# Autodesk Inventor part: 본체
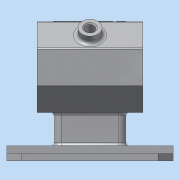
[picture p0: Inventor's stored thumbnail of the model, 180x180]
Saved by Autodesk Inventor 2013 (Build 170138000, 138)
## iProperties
Created: 2018-06
Part Number: 본체
Material: 알루미늄 6061
Document SubType Name: Modeling
Designer: Administrator
Density: 2.71 g/cm^3
Mass: 554.043 g
Surface Area: 601.935 cm^2
Volume: 204.444 cm^3
Author: Administrator
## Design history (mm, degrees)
sketch "스케치1" dims "d18" = 60
  geometry: L1 (0, 30)-(-12.426, 30); L2 (0, 30)-(12.426, 30); L3 (-12.426, 30)-(-30, 12.426); L4 (12.426, 30)-(30, 12.426); L5 (-30, 12.426)-(-30, -12.426); L6 (-30, -12.426)-(-12.426, -30); L7 (-12.426, -30)-(12.426, -30); L8 (30, 12.426)-(30, -12.426); L9 (12.426, -30)-(30, -12.426); 1 further point
  constraints: 18 end point, 4 perpendicular, 2 equal length, 2 horizontal, 1 vertical alignment, 2 other
extrude "돌출1" new body sketch "스케치1" distance "d14" = 35; taper "d16" = 0 deg; dims "d15" = 35, "d17" = 0
sketch "스케치2"
  geometry: C1 r 16 at (0, 0); 1 further point
  constraints: 1 centre point, 1 coincident
  dimensions: "d20" = 32 diameter of C1
extrude "돌출2" cut sketch "스케치2" distance "d21" = 12; taper "d22" = 0 deg
sketch "스케치4"
  geometry: C1 r 16 at (0, 0); 1 further point
  constraints: 1 centre point, 1 coincident
  dimensions: "d26" = 32 diameter of C1
extrude "돌출4" cut sketch "스케치4" distance "d27" = 12; taper "d28" = 0 deg
sketch "스케치5"
  geometry: C1 r 16 at (0, 0) reference; C2 r 14 at (0, 0)
  constraints: 1 centre point, 1 coincident
  dimensions: "d29" = 28 diameter of C2
extrude "돌출5" cut sketch "스케치5" distance "d30" = 3; taper "d31" = 0 deg
sketch "스케치6"
  geometry: C1 r 16 at (0, 0) reference; C2 r 14 at (0, 0)
  constraints: 1 centre point, 1 coincident
  dimensions: "d32" = 28 diameter of C2
extrude "돌출6" cut sketch "스케치6" distance "d33" = 3; taper "d34" = 0 deg
sketch "스케치7"
  geometry: L1 (-14, 20)-(14, 20) reference; L2 (14, -20)-(-14, -20) reference; L3 (0, 20)-(25, 20); L4 (25, 20)-(25, -20); L5 (25, -20)-(0, -20); L6 (0, 20)-(0, -20); 1 further point
  constraints: 8 end point, 2 midpoint, 1 perpendicular, 1 point on line
  dimensions: "d35" = 25 distance of L3.start L3.end; "d36" = 40 distance of L3.end L4.end
revolve "회전1" sketch "스케치7" stored, may be unused: angle "d37" = 90 deg
node "작업 평면1"
sketch "스케치8"
  geometry: L1 (45, -55)-(-45, -55); L2 (-55, -45)-(-55, 45); L3 (-45, 55)-(45, 55); L4 (55, 45)-(55, -45); L5 (55, -55)-(-55, 55); L6 (-55, -55)-(55, 55); L7 (55, -45)-(45, -55); L8 (55, 45)-(45, 55); L9 (-45, 55)-(-55, 45); L10 (-45, -55)-(-55, -45); 1 further point
  constraints: 20 end point, 8 point on line, 2 midpoint, 2 parallel, 1 horizontal, 1 perpendicular
  dimensions: "d39" = 110 distance of L5.end L6.end; "d40" = 110 distance of L6.start L5.end; "d41" = 10 distance of L4.end L5.start; "d42" = 10 distance of L1.start L5.start (= d41); "d43" = 10 distance of L4.start L6.end (= d41); "d44" = 10 distance of L3.end L6.end (= d43); "d45" = 10 distance of L3.start L5.end (= d41); "d46" = 10 distance of L2.end L5.end (= d45); "d47" = 10 distance of L1.end L6.start (= d41); "d48" = 10 distance of L2.start L6.start (= d47)
extrude "돌출7" join sketch "스케치8" distance "d49" = 5; taper "d50" = 0 deg
sketch "스케치9"
  geometry: L1 (-25, 55)-(25, 55); L2 (25, 55)-(25, -55); L3 (25, -55)-(-25, -55); L4 (-25, -55)-(-25, 55); L5 (-25, 55)-(25, -55); L6 (25, 55)-(-25, -55); 1 further point
  constraints: 12 end point, 2 midpoint, 2 parallel, 1 horizontal, 1 perpendicular
  dimensions: "d51" = 50 distance of L2.end L3.end; "d52" = 110 distance of L1.end L2.end
extrude "돌출8" join sketch "스케치9" distance "d53" = 5; taper "d54" = 0 deg
sketch "스케치10"
  geometry: L1 (-55, 45)-(-55, -45) reference; L2 (5, -19)-(5, 19); L3 (-5, 19)-(-5, -19); A1 r 5 centre (0, -19) between (-5, -19) and (5, -19); A2 r 5 centre (0, 19) between (5, 19) and (-5, 19); 1 further point
  constraints: 4 end point, 4 point on circle, 2 centre point, 1 parallel
extrude "돌출9" join sketch "스케치10" stored distance "d59" = 5; taper "d60" = 0 deg
fillet "모깎기1" dims "d61" = 3
fillet "모깎기2" dims "d62" = 0.3
chamfer "모따기1" distance "d63" = 1; stored, may be unused: second distance "d64" = 2, angle "d65" = 45 deg
fillet "모깎기3" dims "d66" = 2
sketch "스케치11"
  geometry: C1 r 17 at (0, 0) reference; A1 r 23 centre (0, 0) between (0, 23) and (-23, 0); 2 further points
  constraints: 4 point on circle, 1 centre point, 1 coincident
  dimensions: "d67" = 46 diameter of A1
hole "구멍1" sketch "스케치11" at (0, 23), (-23, 0), (0, -23), (23, 0) diameter "d68" = 3.242; stored, may be unused: countersink angle "d72" = 90 deg, drill point angle "d74" = 118 deg; dims "d69" = 8, "d70" = 4, "d71" = 2, "d73" = 10
sketch "스케치12"
  geometry: L1 (0, 0)-(0, 37.698); L2 (0, 0)-(21.213, 21.213); L3 (30, 12.426)-(12.426, 30) reference
  constraints: 4 end point, 1 midpoint, 1 vertical
  dimensions: "d76" = 45 deg angle of L1 L2
node "작업 평면2"
sketch "스케치13"
  geometry: C1 r 8 at (0, 0); 1 further point
  constraints: 1 centre point, 1 coincident
  dimensions: "d77" = 16 diameter of C1
extrude "돌출10" join sketch "스케치13" distance "d78" = 7; taper "d79" = 0 deg
sketch "스케치14"
  geometry: C1 r 8 at (0, 0) reference; C2 r 4 at (0, 0)
  constraints: 1 centre point, 1 coincident
  dimensions: "d80" = 8 diameter of C2
extrude "돌출11" cut sketch "스케치14" stored distance "d81" = 7; taper "d82" = 0 deg
chamfer "모따기2" distance "d83" = 1; stored, may be unused: second distance "d84" = 2, angle "d85" = 45 deg
fillet "모깎기4" dims "d86" = 1
fillet "모깎기5" dims "d87" = 3
sketch "스케치15"
  geometry: C1 r 5 at (45, 0); 1 further point
  constraints: 1 centre point
  dimensions: "d89" = 10 diameter of C1
extrude "돌출12" cut sketch "스케치15" stored distance "d90" = 7; taper "d91" = 0 deg
node "작업 평면3"
sketch "스케치16"
  geometry: L1 (-12.012, 35)-(12.012, 35) reference; L2 (30, -35)-(30, 35) reference; 2 further points
  constraints: 1 coincident, 1 other
feature "엠보싱1" sketch "스케치16" dims "d18" = 60, "d93" = 0.5, "d94" = 0
node "솔리드1"
mirror "대칭1"
mirror "대칭2"
other parameters: "d38" = -62, "d92" = 64.75
